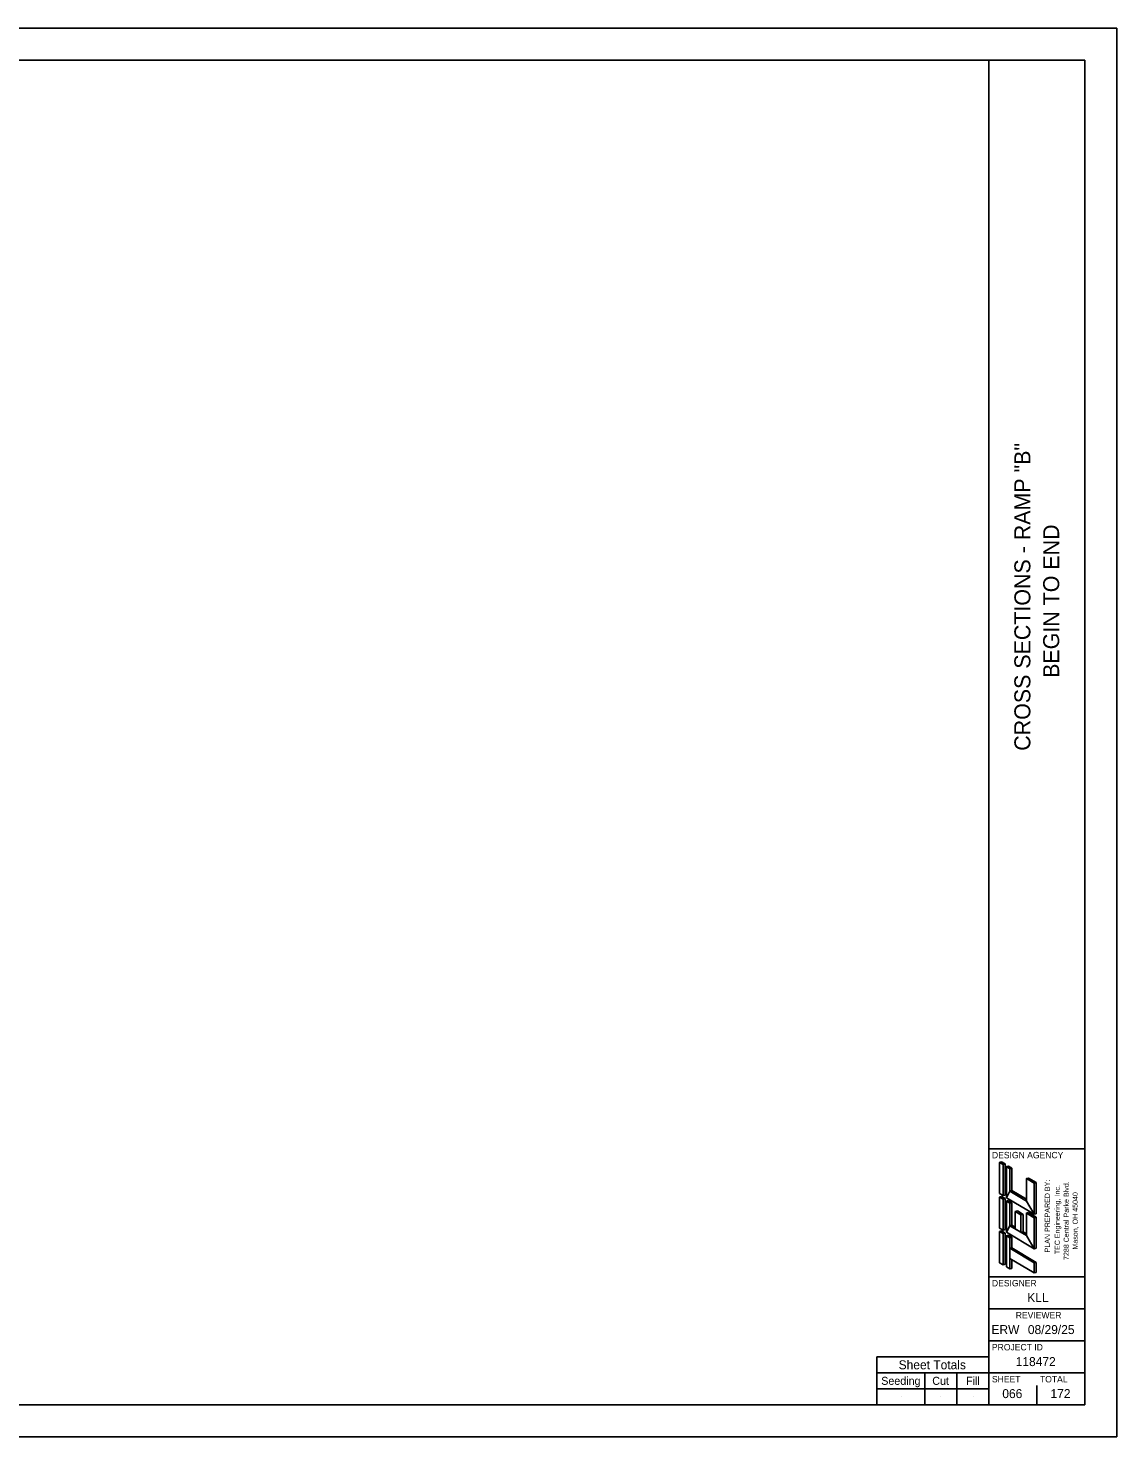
# Model space of a CAD drawing. Extents: x -31.8 to 34, y 0 to 22.
# Drawn here: x 17 to 34, y 0 to 22 of the extents above; entities that cross this region are included whole.
import ezdxf

# ---------------------------------------------------------------- set-up
doc = ezdxf.new("R2010")
doc.units = 0
for name, color, linetype in [('RD_P_GR_Lt', 7, 'Continuous'), ('RD_P_GR_Rt', 7, 'Continuous'), ('RD_P_Median_Barrier', 7, 'Continuous'), ('SH_Named_Boundary', 7, 'Continuous')]:
    doc.layers.add(name, color=color, linetype=linetype)

msp = doc.modelspace()

# ---------------------------------------------------------------- linework, layer by layer
at = {"layer": 'RD_P_GR_Lt'}
msp.add_lwpolyline([(0, 0), (34, 0), (34, 22), (0, 22)], close=True, dxfattribs=at)
at = {"layer": 'RD_P_GR_Rt'}
for p, q in [((32, 0.5), (32, 21.5)), ((32, 4.5), (33.5, 4.5)), ((32, 2.5), (33.5, 2.5)), ((32, 2), (33.5, 2)), ((32, 1.5), (33.5, 1.5)), ((32, 1), (33.5, 1))]:
    msp.add_line(p, q, dxfattribs=at)
msp.add_lwpolyline([(1.5, 21.5), (33.5, 21.5), (33.5, 0.5), (1.5, 0.5)], close=True, dxfattribs=at)
at = {"layer": 'RD_P_Median_Barrier'}
for p, q in [((32.169, 4.285), (32.201, 4.294)), ((32.169, 3.799), (32.169, 4.285)), ((32.223, 4.253), (32.169, 4.285)), ((32.255, 4.261), (32.201, 4.294)), ((32.223, 4.253), (32.255, 4.261)), ((32.223, 3.767), (32.223, 4.253)), ((32.255, 3.775), (32.255, 4.261)), ((32.277, 4.221), (32.309, 4.229)), ((32.331, 4.188), (32.277, 4.221)), ((32.277, 3.735), (32.277, 4.221)), ((32.309, 4.229), (32.363, 4.196)), ((32.331, 4.188), (32.363, 4.196)), ((32.331, 3.837), (32.331, 4.188)), ((32.363, 4.196), (32.363, 3.845)), ((32.587, 4.034), (32.62, 4.042)), ((32.587, 3.683), (32.587, 4.034)), ((32.709, 3.961), (32.587, 4.034)), ((32.62, 4.042), (32.741, 3.97)), ((32.709, 3.961), (32.741, 3.97)), ((32.709, 3.475), (32.709, 3.961)), ((32.741, 3.97), (32.741, 3.484)), ((32.223, 3.767), (32.169, 3.799)), ((32.169, 3.745), (32.201, 3.754)), ((32.169, 3.259), (32.169, 3.745)), ((32.223, 3.713), (32.169, 3.745)), ((32.255, 3.722), (32.201, 3.754)), ((32.223, 3.767), (32.255, 3.775)), ((32.331, 3.837), (32.363, 3.845)), ((32.587, 3.683), (32.331, 3.837)), ((32.363, 3.845), (32.587, 3.711)), ((32.223, 3.713), (32.255, 3.722)), ((32.223, 3.227), (32.223, 3.713)), ((32.255, 3.236), (32.255, 3.722)), ((32.709, 3.475), (32.277, 3.735)), ((32.277, 3.681), (32.309, 3.689)), ((32.277, 3.195), (32.277, 3.681)), ((32.331, 3.648), (32.277, 3.681)), ((32.309, 3.689), (32.363, 3.656)), ((32.331, 3.648), (32.363, 3.656)), ((32.331, 3.297), (32.331, 3.648)), ((32.363, 3.656), (32.363, 3.305)), ((32.415, 3.519), (32.448, 3.527)), ((32.448, 3.527), (32.535, 3.474)), ((32.331, 3.297), (32.363, 3.305)), ((32.363, 3.305), (32.415, 3.274)), ((32.415, 3.519), (32.415, 3.247)), ((32.415, 3.519), (32.503, 3.466)), ((32.503, 3.466), (32.535, 3.474)), ((32.503, 3.466), (32.503, 3.194)), ((32.535, 3.474), (32.535, 3.202)), ((32.587, 3.494), (32.62, 3.502)), ((32.587, 3.143), (32.587, 3.494)), ((32.709, 3.421), (32.587, 3.494)), ((32.62, 3.502), (32.741, 3.43)), ((32.709, 3.475), (32.741, 3.484)), ((32.709, 3.421), (32.741, 3.43)), ((32.709, 2.935), (32.709, 3.421)), ((32.741, 3.43), (32.741, 2.944)), ((32.223, 3.227), (32.169, 3.259)), ((32.169, 3.205), (32.201, 3.215)), ((32.169, 2.719), (32.169, 3.205)), ((32.223, 3.173), (32.169, 3.205)), ((32.255, 3.181), (32.201, 3.215)), ((32.222, 3.173), (32.255, 3.181)), ((32.223, 3.227), (32.255, 3.236)), ((32.223, 2.687), (32.223, 3.173)), ((32.255, 2.695), (32.255, 3.181)), ((32.709, 2.935), (32.277, 3.195)), ((32.277, 3.141), (32.309, 3.151)), ((32.331, 3.108), (32.277, 3.141)), ((32.277, 2.655), (32.277, 3.141)), ((32.309, 3.151), (32.363, 3.116)), ((32.415, 3.247), (32.331, 3.297)), ((32.331, 3.108), (32.363, 3.116)), ((32.331, 2.944), (32.331, 3.108)), ((32.363, 3.116), (32.363, 2.952)), ((32.503, 3.194), (32.535, 3.202)), ((32.587, 3.143), (32.503, 3.194)), ((32.535, 3.202), (32.587, 3.171)), ((32.331, 2.944), (32.363, 2.952)), ((32.331, 2.944), (32.709, 2.717)), ((32.363, 2.952), (32.741, 2.725)), ((32.709, 2.935), (32.741, 2.944)), ((32.223, 2.687), (32.169, 2.719)), ((32.223, 2.687), (32.255, 2.695)), ((32.331, 2.622), (32.277, 2.655)), ((32.331, 2.787), (32.709, 2.56)), ((32.331, 2.622), (32.331, 2.787)), ((32.363, 2.63), (32.363, 2.767)), ((32.709, 2.717), (32.741, 2.725)), ((32.709, 2.56), (32.709, 2.717)), ((32.741, 2.725), (32.741, 2.568)), ((32.331, 2.622), (32.363, 2.63)), ((32.709, 2.56), (32.741, 2.568))]:
    msp.add_line(p, q, dxfattribs=at)
for points in [[(32.169, 3.799), (32.223, 3.767), (32.223, 4.253), (32.169, 4.285)], [(32.277, 3.735), (32.331, 3.837), (32.331, 4.188), (32.277, 4.221)], [(32.709, 3.475), (32.587, 3.683), (32.587, 4.034), (32.709, 3.961)], [(32.169, 3.259), (32.223, 3.227), (32.223, 3.713), (32.169, 3.745)], [(32.277, 3.735), (32.331, 3.837), (32.587, 3.683), (32.709, 3.475)], [(32.277, 3.195), (32.331, 3.297), (32.331, 3.648), (32.277, 3.681)], [(32.415, 3.247), (32.415, 3.519), (32.503, 3.466), (32.503, 3.194)], [(32.709, 2.935), (32.587, 3.143), (32.587, 3.494), (32.709, 3.421)], [(32.169, 2.719), (32.223, 2.687), (32.223, 3.173), (32.169, 3.205)], [(32.277, 3.195), (32.331, 3.297), (32.587, 3.143), (32.709, 2.935)], [(32.277, 2.655), (32.331, 2.622), (32.331, 3.108), (32.277, 3.141)], [(32.331, 2.787), (32.331, 2.944), (32.709, 2.717), (32.709, 2.56)]]:
    msp.add_lwpolyline(points, close=True, dxfattribs=at)
at = {"layer": 'SH_Named_Boundary'}
for p, q in [((32.75, 3.5), (32.75, 3.5)), ((30.25, 0.5), (30.25, 1.25)), ((30.25, 1.25), (32, 1.25)), ((30.25, 1), (32, 1)), ((31, 0.5), (31, 1)), ((31.5, 0.5), (31.5, 1)), ((30.25, 0.75), (32, 0.75)), ((32.375, 0.675), (32.375, 0.675)), ((32.75, 0.5), (32.75, 0.8)), ((30.632, 0.625), (30.632, 0.625)), ((31.254, 0.625), (31.254, 0.625)), ((31.76, 0.625), (31.76, 0.625))]:
    msp.add_line(p, q, dxfattribs=at)

# ---------------------------------------------------------------- texts
at = {"layer": 'RD_P_Median_Barrier'}
for s, p in [('PLAN PREPARED BY:', (32.954, 2.88)), ('TEC Engineering, Inc.', (33.11, 2.851)), ('7288 Central Parke Blvd.', (33.25, 2.762)), ('Mason, OH 45040', (33.39, 2.925))]:
    msp.add_text(s, height=0.08, rotation=90, dxfattribs=at).set_placement(p)
at = {"layer": 'SH_Named_Boundary'}
for s, p in [('CROSS SECTIONS - RAMP "B"', (32.65, 10.715)), ('BEGIN TO END', (33.1, 11.853))]:
    msp.add_text(s, height=0.25, rotation=90, dxfattribs=at).set_placement(p)
for s, height, p in [('DESIGN AGENCY', 0.1, (32.05, 4.35)), ('DESIGNER', 0.1, (32.05, 2.35)), ('KLL', 0.14, (32.601, 2.105)), ('REVIEWER', 0.1, (32.422, 1.85)), ('ERW', 0.14, (32.042, 1.605)), ('08/29/25', 0.14, (32.611, 1.605)), ('PROJECT ID', 0.1, (32.05, 1.35)), ('Sheet Totals', 0.14, (30.593, 1.055)), ('118472', 0.14, (32.421, 1.105)), ('Seeding', 0.125, (30.321, 0.812)), ('Cut', 0.125, (31.118, 0.812)), ('Fill', 0.125, (31.646, 0.812)), ('SHEET', 0.1, (32.05, 0.85)), ('TOTAL', 0.1, (32.8, 0.85)), ('066', 0.14, (32.212, 0.605)), ('172', 0.14, (32.964, 0.605))]:
    msp.add_text(s, height=height, dxfattribs=at).set_placement(p)

doc.saveas('drawing.dxf')
